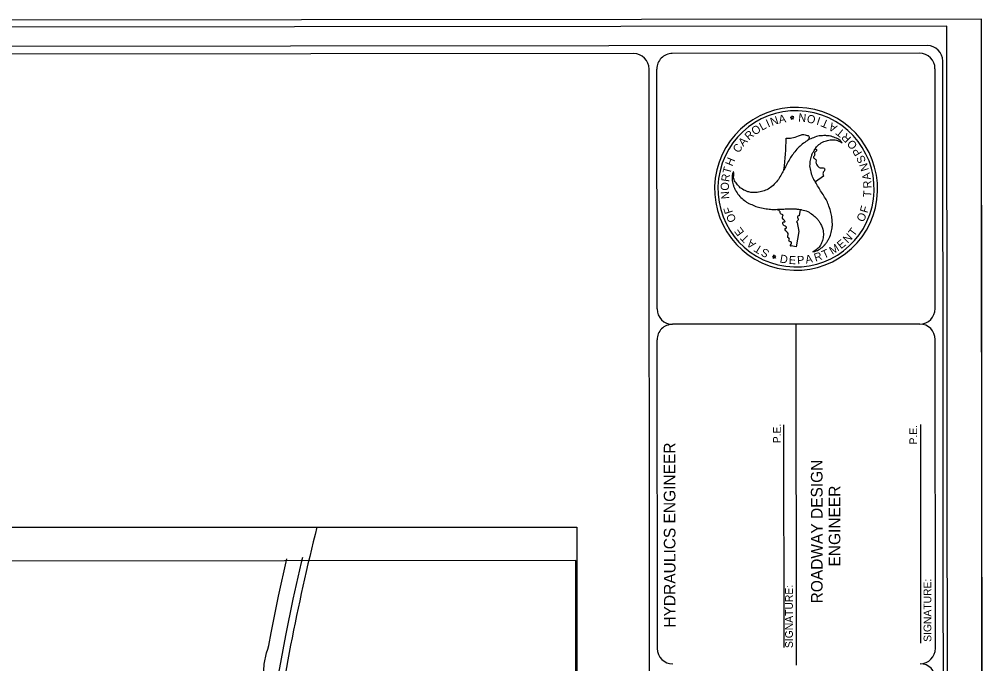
# Model space of a CAD drawing. Extents: x 1372027 to 1374286, y 553832 to 556743.
# Drawn here: x 1373560 to 1374184, y 555100 to 555517 of the extents above; entities that cross this region are included whole.
import ezdxf

# ---------------------------------------------------------------- set-up
doc = ezdxf.new("R2010")
doc.units = 0
for name, color, linetype in [('Prop Approach Slab', 7, 'Continuous'), ('Prop Approach Slab Hatching', 7, 'Continuous'), ('Prop Dimension Text', 7, 'Continuous'), ('Prop Roadway Bridge', 7, 'Continuous'), ('Prop Structure Anchor Unit CELL', 7, 'Continuous'), ('Prop Terminator CELL', 7, 'Continuous'), ('Sheet Clip Boundary CELL', 7, 'Continuous'), ('Sheet Plot Border Inside CELL', 7, 'Continuous')]:
    doc.layers.add(name, color=color, linetype=linetype)

msp = doc.modelspace()

# ---------------------------------------------------------------- linework, layer by layer
at = {"layer": 'Prop Approach Slab'}
msp.add_lwpolyline([(1374161.39, 553845.95), (1374159.91, 555512.45), (1373104.81, 555511.51), (1373106.29, 553845.01)], close=True, dxfattribs=at)
at = {"layer": 'Prop Approach Slab Hatching'}
msp.add_lwpolyline([(1373082.36, 555515.99), (1373083.86, 553831.99), (1374183.84, 553832.97), (1374182.35, 555516.97)], close=True, dxfattribs=at)
at = {"layer": 'Prop Dimension Text'}
msp.add_lwpolyline([(1373448.16, 554513.79), (1373448.16, 555188.2), (1373920.65, 555188.2), (1373920.65, 554513.79)], close=True, dxfattribs=at)
at = {"layer": 'Prop Roadway Bridge'}
for p, q in [((1373968.64, 554064.77), (1373967.37, 555484.77)), ((1373972.51, 555329.55), (1373972.37, 555484.78)), ((1374069.34, 555459.5), (1374069.34, 555459.5)), ((1374059.58, 555453.67), (1374058.71, 555453.47)), ((1374058.71, 555453.47), (1374059.51, 555453.08)), ((1374059.51, 555453.08), (1374059.39, 555452.18)), ((1374059.39, 555452.18), (1374060.01, 555452.85)), ((1374059.67, 555454.55), (1374059.58, 555453.67)), ((1374060.13, 555453.75), (1374059.67, 555454.55)), ((1374060.01, 555452.85), (1374060.84, 555452.48)), ((1374061.03, 555453.9), (1374060.13, 555453.75)), ((1374060.41, 555453.24), (1374061.03, 555453.9)), ((1374060.84, 555452.48), (1374060.41, 555453.24)), ((1374021.77, 555418.25), (1374021.87, 555418.15)), ((1374021.77, 555418.25), (1374021.87, 555418.15)), ((1374054.61, 555419.6), (1374054.61, 555419.6)), ((1374080.26, 555415.46), (1374074.92, 555411.7)), ((1374074.92, 555411.7), (1374074.92, 555411.7)), ((1374065.07, 555393.95), (1374064.48, 555389.82)), ((1374063.25, 555385.54), (1374064.17, 555379.63)), ((1374064.17, 555379.63), (1374062.49, 555369.77)), ((1374062.49, 555369.77), (1374059.36, 555370.29)), ((1374047.1, 555363.37), (1374047.98, 555363.57)), ((1374047.98, 555363.57), (1374048.09, 555364.47)), ((1374048.09, 555364.47), (1374048.54, 555363.65)), ((1374048.54, 555363.65), (1374049.44, 555363.81)), ((1374049.44, 555363.81), (1374048.8, 555363.14)), ((1374047.9, 555363.01), (1374047.1, 555363.37)), ((1374047.78, 555362.1), (1374047.9, 555363.01)), ((1374048.42, 555362.75), (1374047.78, 555362.1)), ((1374049.25, 555362.37), (1374048.42, 555362.75)), ((1374048.8, 555363.14), (1374049.25, 555362.37)), ((1374142.52, 555319.7), (1373982.52, 555319.56)), ((1374062.69, 555098.96), (1374062.5, 555319.63)), ((1373972.71, 555109.78), (1373972.53, 555309.55)), ((1374054.7, 555110.35), (1374054.57, 555254.6)), ((1374143.26, 555113.18), (1374143.14, 555254.68))]:
    msp.add_line(p, q, dxfattribs=at)
for points in [[(1374147.36, 555499.93), (1373117.37, 555499.02)], [(1373957.38, 555494.76), (1373122.37, 555494.02)], [(1374142.37, 555494.93), (1373982.37, 555494.79)], [(1374158.7, 554009.94), (1374157.38, 555489.94)], [(1374152.51, 555329.71), (1374152.37, 555484.94)], [(1374152.71, 555109.94), (1374152.53, 555309.71)]]:
    msp.add_lwpolyline(points, dxfattribs=at)
for centre, radius, start, end in [((1373957.33, 555484.77), 10, 0.05095, 90.05095), ((1373982.33, 555484.79), 10, 90.05095, 180.05095), ((1374142.33, 555484.93), 10, 0.05095, 90.05095), ((1374147.33, 555489.94), 10, 0.05095, 90.05095), ((1374062.44, 555407.24), 52.72, 82.47208, 262.47208), ((1374062.44, 555407.24), 50.52, 82.47208, 262.47208), ((1374062.44, 555407.24), 52.72, 262.47208, 82.47208), ((1374062.44, 555407.24), 50.52, 262.47208, 82.47208), ((1373778.4, 555450.63), 277.94, 353.58963, 357.79564), ((1373778.4, 555450.63), 277.94, 348.15057, 348.25017), ((1373982.51, 555329.56), 10, 180.05095, 270.05095), ((1374142.46, 555329.7), 10, 270.05095, 0.05095), ((1373982.53, 555309.56), 10, 90.05095, 180.05095), ((1374142.47, 555309.7), 10, 0.05095, 90.05095), ((1373982.66, 555109.79), 10, 180.05095, 270.05095), ((1374142.66, 555109.93), 10, 270.05095, 0.05095), ((1374142.68, 555089.93), 10, 0.05095, 90.05095)]:
    msp.add_arc(centre, radius, start, end, dxfattribs=at)
for points in [[(1374092.27, 555436.99), (1374091.54, 555437.91), (1374088.68, 555439.96), (1374085.16, 555441.22), (1374084.81, 555441.32), (1374082.81, 555441.61), (1374080.44, 555441.66), (1374076.53, 555441.29), (1374072.79, 555439.94), (1374071.22, 555439.38), (1374069.62, 555438.36), (1374066.44, 555436.13), (1374063.76, 555433.67), (1374061.04, 555430.46), (1374058.87, 555427.49), (1374057, 555424.13), (1374055.23, 555420.73), (1374053.43, 555417.5), (1374051.5, 555414.12), (1374049.24, 555411.16), (1374049, 555410.92), (1374046.01, 555408.1), (1374042.58, 555406.32), (1374039.14, 555405.22), (1374037.35, 555404.96), (1374035.1, 555404.94), (1374033.8, 555404.87), (1374031.19, 555405.41), (1374027.78, 555406.93), (1374025.14, 555409.22), (1374023.15, 555411.77), (1374022.05, 555414.86), (1374021.87, 555418.15), (1374021.77, 555418.25)], [(1374070.61, 555439.07), (1374069.62, 555438.36), (1374066.44, 555436.13), (1374063.76, 555433.67), (1374061.04, 555430.46), (1374058.87, 555427.49), (1374057, 555424.13), (1374055.23, 555420.73), (1374054.61, 555419.6)], [(1374056.15, 555439.94), (1374059.73, 555440.22), (1374064.08, 555441.5), (1374066.48, 555442.39), (1374068.41, 555442.1), (1374070.66, 555441.34), (1374070.6, 555439.08)], [(1374073.37, 555366.56), (1374074.6, 555366.78), (1374077.78, 555368.23), (1374080.65, 555370.63), (1374080.85, 555370.9), (1374082.17, 555372.48), (1374083.35, 555374.5), (1374085, 555378.09), (1374085.7, 555381.97), (1374085.99, 555383.62), (1374085.9, 555385.57), (1374085.56, 555389.37), (1374084.78, 555392.91), (1374083.37, 555396.91), (1374081.9, 555400.25), (1374079.89, 555403.54), (1374077.82, 555406.78), (1374075.92, 555409.99), (1374074.02, 555413.32), (1374072.53, 555416.78), (1374072.44, 555417.15), (1374071.52, 555421.12), (1374071.67, 555424.94), (1374072.45, 555428.44), (1374073.08, 555430.23), (1374074.23, 555432.11), (1374074.81, 555433.31), (1374076.57, 555435.3), (1374079.58, 555437.44), (1374082.89, 555438.61), (1374086.12, 555439.06), (1374089.33, 555438.48), (1374092.27, 555436.99)], [(1374074.92, 555411.7), (1374074.02, 555413.32), (1374072.53, 555416.78), (1374072.44, 555417.15), (1374071.52, 555421.12), (1374071.67, 555424.94), (1374072.45, 555428.44), (1374073.08, 555430.23), (1374074.23, 555432.11), (1374074.79, 555433.22)], [(1374074.8, 555433.2), (1374075.65, 555432.6), (1374075.61, 555431.8), (1374074.32, 555430.57), (1374074.44, 555428.83), (1374073.89, 555428.12), (1374073.81, 555427.61), (1374075.18, 555426.18), (1374075.33, 555424.46), (1374076.97, 555421.49), (1374078.06, 555420.78), (1374080.59, 555420.65), (1374081, 555419.91), (1374080.77, 555419.12), (1374079.9, 555417.54), (1374080.26, 555415.46)], [(1374021.87, 555418.15), (1374021.4, 555417.01), (1374021.09, 555413.52), (1374021.75, 555409.84), (1374021.88, 555409.51), (1374022.58, 555407.62), (1374023.72, 555405.56), (1374026.03, 555402.37), (1374029.04, 555399.77), (1374030.33, 555398.71), (1374031.99, 555397.85), (1374035.52, 555396.2), (1374039, 555395.12), (1374043.14, 555394.34), (1374046.8, 555393.92), (1374050.62, 555394.03), (1374054.47, 555394.18), (1374058.19, 555394.24), (1374062.02, 555394.26), (1374065.76, 555393.78), (1374066.08, 555393.72), (1374069.98, 555392.53), (1374073.25, 555390.46), (1374075.9, 555387.99), (1374077.09, 555386.59), (1374078.22, 555384.66), (1374078.88, 555383.57), (1374079.77, 555381.04), (1374080.14, 555377.35), (1374079.47, 555373.87), (1374078.27, 555370.88), (1374076.16, 555368.38), (1374073.37, 555366.56)], [(1374059.36, 555370.29), (1374059.05, 555370.22), (1374058.78, 555370.79), (1374059.58, 555372.18), (1374059.04, 555373.01), (1374058.4, 555373.06), (1374057.85, 555373.74), (1374058.18, 555374.72), (1374057.14, 555375.78), (1374057.05, 555376.65), (1374057.28, 555378.41), (1374055.45, 555380.78), (1374055.45, 555381.68), (1374056.03, 555381.83), (1374056.21, 555382.35), (1374054.6, 555383.48), (1374054.38, 555383.75), (1374053.94, 555385.47), (1374054.31, 555385.87), (1374055.1, 555385.89), (1374055.29, 555386.1), (1374054.97, 555386.69), (1374054.14, 555387.54), (1374053.62, 555388.98), (1374054.01, 555390.49), (1374052.79, 555390.92), (1374051.82, 555392.88), (1374051.14, 555393.35), (1374050.41, 555393.54)], [(1374050.52, 555394.03), (1374050.62, 555394.03), (1374054.47, 555394.18), (1374058.19, 555394.24), (1374062.02, 555394.26), (1374065.07, 555393.93)], [(1374064.48, 555389.82), (1374063.67, 555389.52), (1374063.33, 555388.74), (1374063.76, 555387.58), (1374063.6, 555386.77), (1374062.83, 555385.95), (1374063.25, 555385.54)]]:
    msp.add_spline(points, degree=3, dxfattribs=at)
at = {"layer": 'Prop Structure Anchor Unit CELL'}
msp.add_line((1374183.84, 553832.97), (1374182.35, 555516.97), dxfattribs=at)
at = {"layer": 'Prop Terminator CELL'}
msp.add_arc((1375172.7, 554831.81), 1464.32, 165.9137, 172.027, dxfattribs=at)
at = {"layer": 'Sheet Clip Boundary CELL'}
msp.add_lwpolyline([(1373920.63, 554536.72), (1373920.07, 555166.73), (1373542.74, 555166.39), (1373542.82, 555081.22), (1373447.65, 555081.14), (1373448.5, 554711.84), (1373547.67, 554711.94), (1373547.83, 554537.32)], close=True, dxfattribs=at)
at = {"layer": 'Sheet Plot Border Inside CELL'}
for points in [[(1373701.61, 554851.79), (1373701.21, 554870.75), (1373700.2, 554893.75), (1373699.62, 554920.02), (1373700.18, 554945.38), (1373701.21, 554970.07), (1373703.46, 554994.03), (1373703.11, 554996.83), (1373704.03, 555005.17), (1373704.94, 555007.48), (1373706.87, 555021.03), (1373710.29, 555045.83), (1373714.09, 555070.37), (1373718.12, 555095.57), (1373718.29, 555099.56), (1373719.79, 555107.01), (1373720.66, 555109.37), (1373721.37, 555111.69), (1373722.93, 555119.85), (1373727.71, 555143.54), (1373732.97, 555167.75)], [(1373743.23, 555168.72), (1373742.35, 555165.46), (1373736.85, 555141.77), (1373732.18, 555118.17), (1373727.58, 555093.88), (1373723.31, 555069.18), (1373719.46, 555044.41), (1373715.92, 555019.44), (1373712.89, 554994.91), (1373710.72, 554969.19), (1373709.46, 554944.12), (1373709.13, 554919.48), (1373709.47, 554894.39), (1373710.94, 554870.53), (1373712.05, 554852.76)]]:
    msp.add_lwpolyline(points, dxfattribs=at)

# ---------------------------------------------------------------- texts
at = {"layer": 'Prop Roadway Bridge'}
for s, height, rotation, p in [('I', 5.26, 24.06752, (1374044.41, 555446.88)), ('N', 5.25, 18.36742, (1374046.76, 555447.89)), ('A', 5.26, 10.93544, (1374051.67, 555449.48)), ('N', 5.26, 174.68021, (1374069.27, 555455.65)), ('O', 5.24, 167.4322, (1374075.48, 555454.32)), ('I', 5.27, 162.29657, (1374078.7, 555453.33)), ('T', 5.25, 156.64666, (1374084.16, 555451)), ('R', 5.25, 41.41014, (1374031.95, 555438.36)), ('O', 5.27, 34.29054, (1374035.73, 555441.67)), ('L', 5.24, 28.05686, (1374040.35, 555444.83)), ('A', 5.27, 149.56224, (1374089.57, 555447.91)), ('T', 5.24, 141.4752, (1374094.29, 555444.27)), ('A', 5.25, 47.77409, (1374028.33, 555434.36)), ('R', 5.27, 135.37541, (1374098.49, 555440.24)), ('O', 5.27, 128.1863, (1374102.45, 555435.27)), ('C', 5.24, 55.27112, (1374025.32, 555430.06)), ('P', 5.25, 121.49431, (1374105.43, 555430.49)), ('H', 5.25, 67.61347, (1374021.25, 555421.46)), ('S', 5.23, 114.30246, (1374107.85, 555425.21)), ('T', 5.27, 74.69819, (1374019.86, 555416.5)), ('N', 5.24, 107.09199, (1374109.7, 555419.56)), ('R', 5.26, 81.34782, (1374019.1, 555411.53)), ('A', 5.24, 100.06036, (1374110.88, 555413.46)), ('O', 5.27, 87.95775, (1374018.91, 555405.98)), ('R', 5.26, 93.30723, (1374111.3, 555407.67)), ('N', 5.26, 95.45586, (1374019.36, 555400.86)), ('T', 5.24, 86.35061, (1374110.99, 555401.72)), ('F', 5.27, 107.5428, (1374021.65, 555392)), ('F', 5.25, 73.44138, (1374108.59, 555391.24)), ('O', 5.26, 114.68964, (1374023.94, 555386.93)), ('O', 5.25, 66.27615, (1374106.12, 555385.39)), ('E', 5.24, 126.62902, (1374029.13, 555379.19)), ('T', 5.25, 52.97246, (1374099.98, 555376)), ('T', 5.24, 133.74465, (1374032.67, 555375.46)), ('N', 5.27, 46.13046, (1374095.91, 555371.69)), ('A', 5.27, 140.79987, (1374036.88, 555372.02)), ('T', 5.27, 147.85218, (1374041.19, 555369.22)), ('M', 5.24, 31.69215, (1374085.92, 555364.45)), ('E', 5.24, 39.15892, (1374091.55, 555368.05)), ('S', 5.25, 154.22833, (1374045.69, 555367.04)), ('D', 5.26, 350.32508, (1374051.65, 555359.63)), ('E', 5.23, 356.61297, (1374057.61, 555358.67)), ('P', 5.26, 4.14536, (1374063.31, 555358.44)), ('A', 5.25, 10.73793, (1374068.91, 555358.85)), ('R', 5.26, 17.80657, (1374075.02, 555360.07)), ('T', 5.25, 24.4571, (1374080.52, 555361.9)), ('P.E.', 5, 90.05095, (1374052.54, 555242.63)), ('P.E.', 5, 90.05095, (1374140.74, 555241.83)), (' HYDRAULICS ENGINEER', 7.5, 90.05095, (1373984.46, 555120.49)), ('ROADWAY DESIGN', 7.4994, 90.05095, (1374079.63, 555138.97)), ('ENGINEER', 7.499, 90.05095, (1374091.11, 555162.83)), ('SIGNATURE:', 5, 90.05095, (1374149.95, 555114.09)), ('SIGNATURE:', 5, 90.05095, (1374060.39, 555110.08))]:
    msp.add_text(s, height=height, rotation=rotation, dxfattribs=at).set_placement(p)

doc.saveas('drawing.dxf')
